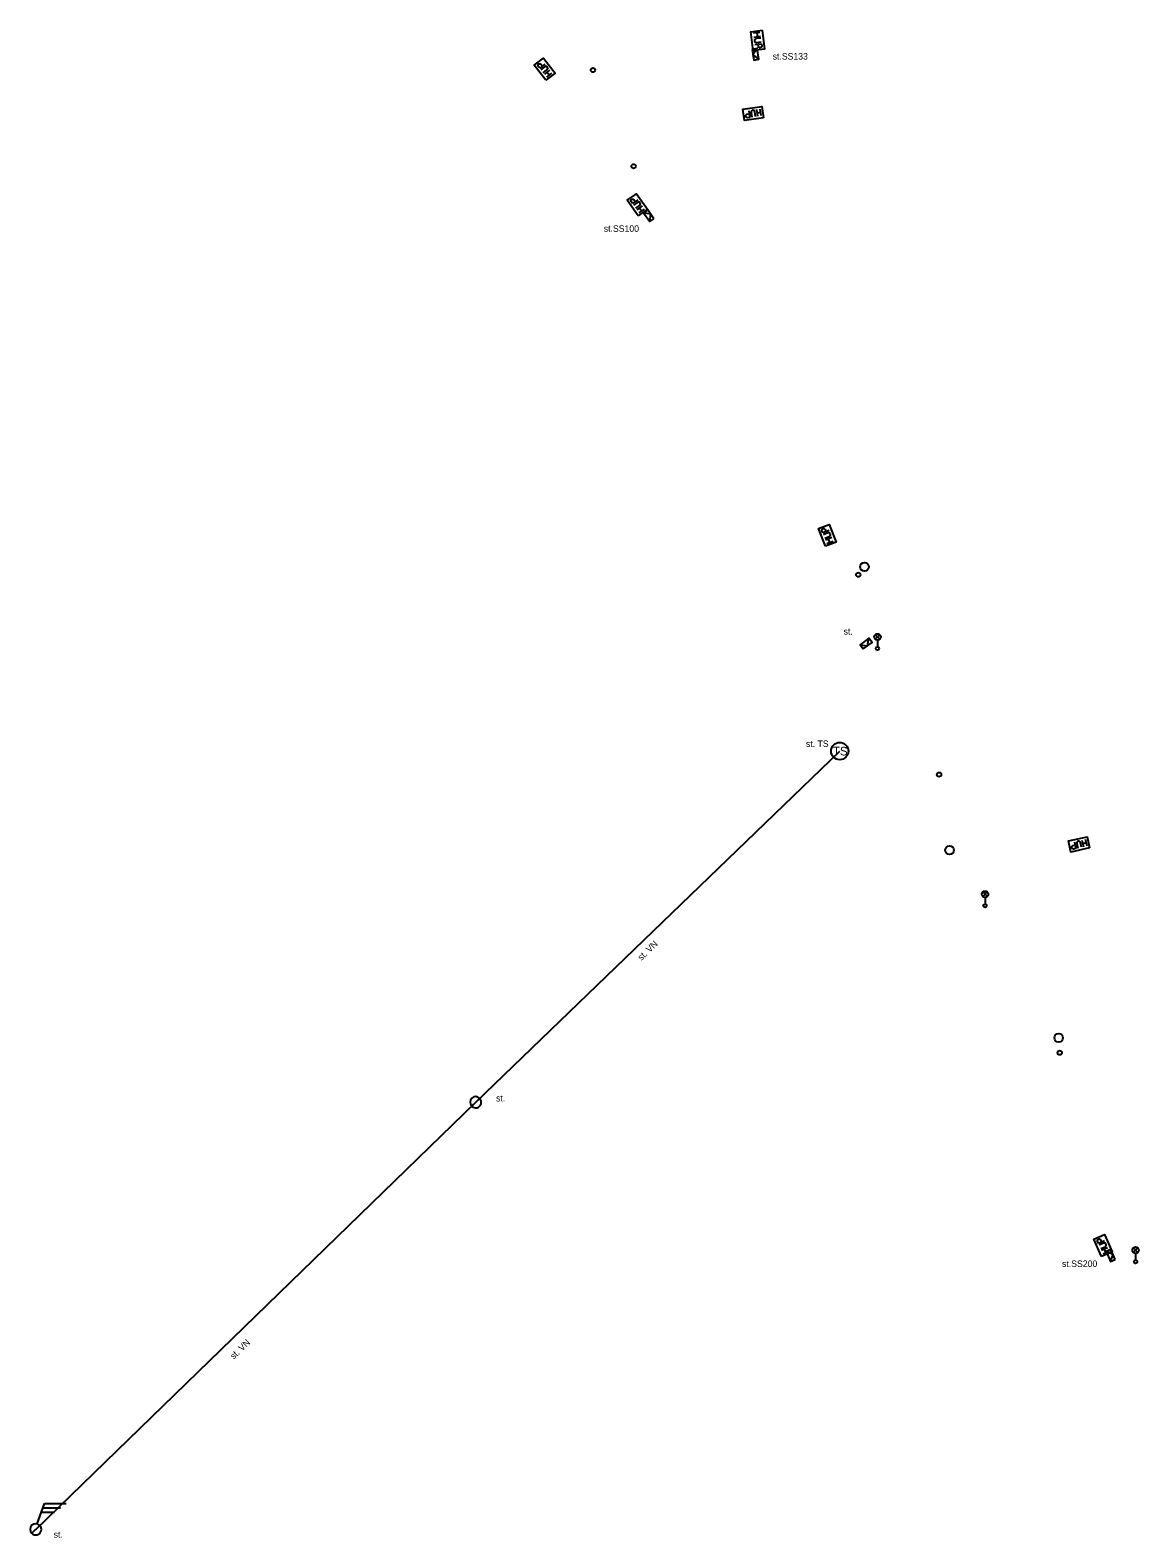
# Model space of a CAD drawing. Extents: x -762500 to -761250, y -1152983 to -1152297.
# Drawn here: x -761610 to -761481.9, y -1152711 to -1152536.8 of the extents above; entities that cross this region are included whole.
import ezdxf

# ---------------------------------------------------------------- set-up
doc = ezdxf.new("R2010")
doc.units = 0
for name, color, linetype in [('Vrstva 1', 7, 'Continuous'), ('Vrstva 2', 7, 'Continuous'), ('Vrstva 9', 7, 'Continuous')]:
    doc.layers.add(name, color=color, linetype=linetype)

msp = doc.modelspace()

# ---------------------------------------------------------------- linework, layer by layer
at = {"layer": 'Vrstva 1'}
for p, q in [((-761558.052, -1152660.189), (-761558.988, -1152661.091)), ((-761609.205, -1152709.33), (-761608.35, -1152706.98)), ((-761608.7, -1152707.98), (-761607.2, -1152707.98)), ((-761608.5, -1152707.48), (-761606.5, -1152707.48)), ((-761608.35, -1152706.98), (-761605.85, -1152706.98)), ((-761608.884, -1152709.527), (-761609.816, -1152710.433))]:
    msp.add_line(p, q, dxfattribs=at)
for points in [[(-761526.572, -1152539.012), (-761526.388, -1152540.248), (-761525.795, -1152540.16), (-761525.978, -1152538.924)], [(-761537.924, -1152558.573), (-761538.636, -1152557.547), (-761539.129, -1152557.889), (-761538.417, -1152558.916)], [(-761513.734, -1152608.269), (-761512.726, -1152607.531), (-761513.08, -1152607.047), (-761514.089, -1152607.785)], [(-761484.63, -1152678.793), (-761485.13, -1152677.647), (-761485.68, -1152677.887), (-761485.18, -1152679.033)]]:
    msp.add_lwpolyline(points, close=True, dxfattribs=at)
for points in [[(-761525.978, -1152538.924), (-761526.48, -1152539.63), (-761525.795, -1152540.16)], [(-761538.417, -1152558.916), (-761538.28, -1152558.06), (-761539.129, -1152557.889)], [(-761514.089, -1152607.785), (-761513.23, -1152607.9), (-761513.08, -1152607.047)], [(-761609.35, -1152709.98), (-761558.52, -1152660.64), (-761516.46, -1152620.08)], [(-761485.18, -1152679.033), (-761484.88, -1152678.22), (-761485.68, -1152677.887)]]:
    msp.add_lwpolyline(points, dxfattribs=at)
msp.add_circle((-761516.46, -1152620.08), 1, dxfattribs=at)
for centre, start, end in [((-761558.52, -1152660.64), 43.95968, 223.95968), ((-761558.52, -1152660.64), 223.95968, 43.95968), ((-761609.35, -1152709.98), 44.14761, 224.14761), ((-761609.35, -1152709.98), 224.14761, 44.14761)]:
    msp.add_arc(centre, 0.65, start, end, dxfattribs=at)
at = {"layer": 'Vrstva 9'}
for p, q in [((-761512.364, -1152607.158), (-761511.836, -1152606.63)), ((-761511.828, -1152607.155), (-761512.356, -1152606.626)), ((-761512.1, -1152607.27), (-761512.1, -1152608.02)), ((-761499.934, -1152636.878), (-761499.406, -1152636.35)), ((-761499.398, -1152636.875), (-761499.926, -1152636.346)), ((-761499.67, -1152636.99), (-761499.67, -1152637.74)), ((-761482.534, -1152677.988), (-761482.006, -1152677.46)), ((-761481.998, -1152677.985), (-761482.526, -1152677.456)), ((-761482.27, -1152678.1), (-761482.27, -1152678.85))]:
    msp.add_line(p, q, dxfattribs=at)
for points in [[(-761525.428, -1152536.794), (-761525.136, -1152538.975), (-761526.444, -1152539.15), (-761526.736, -1152536.97), (-761525.428, -1152536.794)], [(-761525.671, -1152537.049), (-761526.434, -1152537.151)], [(-761526.031, -1152537.097), (-761525.972, -1152537.535)], [(-761526.376, -1152537.589), (-761525.612, -1152537.487)], [(-761525.584, -1152537.703), (-761526.131, -1152537.776), (-761526.234, -1152537.822), (-761526.297, -1152537.899), (-761526.321, -1152537.996), (-761526.313, -1152538.058), (-761526.264, -1152538.145), (-761526.183, -1152538.198), (-761526.072, -1152538.215), (-761525.525, -1152538.141)], [(-761526.259, -1152538.46), (-761525.496, -1152538.357)], [(-761525.496, -1152538.357), (-761525.458, -1152538.641), (-761525.482, -1152538.737), (-761525.514, -1152538.774), (-761525.581, -1152538.815), (-761525.69, -1152538.829), (-761525.766, -1152538.808), (-761525.805, -1152538.78), (-761525.854, -1152538.694), (-761525.892, -1152538.41)], [(-761550.399, -1152542.578), (-761551.747, -1152540.839), (-761550.704, -1152540.031), (-761549.356, -1152541.769), (-761550.399, -1152542.578)], [(-761551.125, -1152541.192), (-761551.301, -1152540.966), (-761551.328, -1152540.871), (-761551.32, -1152540.823), (-761551.282, -1152540.754), (-761551.195, -1152540.687), (-761551.118, -1152540.667), (-761551.07, -1152540.671), (-761550.985, -1152540.721), (-761550.809, -1152540.947)], [(-761550.517, -1152540.721), (-761551.125, -1152541.192)], [(-761550.721, -1152541.714), (-761550.285, -1152541.376), (-761550.219, -1152541.285), (-761550.202, -1152541.187), (-761550.23, -1152541.091), (-761550.269, -1152541.041), (-761550.355, -1152540.99), (-761550.451, -1152540.985), (-761550.556, -1152541.027), (-761550.992, -1152541.365)], [(-761549.979, -1152541.415), (-761550.588, -1152541.886)], [(-761550.317, -1152542.236), (-761549.708, -1152541.764)], [(-761550.03, -1152542.013), (-761550.301, -1152541.664)], [(-761525.274, -1152546.91), (-761527.449, -1152547.24), (-761527.648, -1152545.935), (-761525.472, -1152545.605), (-761525.274, -1152546.91)], [(-761526.086, -1152545.976), (-761525.97, -1152546.737)], [(-761525.533, -1152546.671), (-761525.649, -1152545.91)], [(-761526.838, -1152546.869), (-761527.121, -1152546.912), (-761527.217, -1152546.889), (-761527.255, -1152546.859), (-761527.297, -1152546.792), (-761527.313, -1152546.684), (-761527.294, -1152546.607), (-761527.266, -1152546.567), (-761527.181, -1152546.517), (-761526.898, -1152546.474)], [(-761526.954, -1152546.108), (-761526.838, -1152546.869)], [(-761526.185, -1152546.77), (-761526.268, -1152546.224), (-761526.315, -1152546.122), (-761526.393, -1152546.06), (-761526.491, -1152546.038), (-761526.553, -1152546.047), (-761526.64, -1152546.098), (-761526.691, -1152546.179), (-761526.705, -1152546.291), (-761526.622, -1152546.836)], [(-761525.588, -1152546.312), (-761526.025, -1152546.378)], [(-761539.744, -1152558.25), (-761541.013, -1152556.452), (-761539.934, -1152555.691), (-761538.666, -1152557.489), (-761539.744, -1152558.25)], [(-761540.407, -1152556.833), (-761540.572, -1152556.599), (-761540.595, -1152556.503), (-761540.585, -1152556.455), (-761540.544, -1152556.388), (-761540.454, -1152556.325), (-761540.377, -1152556.308), (-761540.329, -1152556.315), (-761540.246, -1152556.369), (-761540.081, -1152556.602)], [(-761539.778, -1152556.389), (-761540.407, -1152556.833)], [(-761540.027, -1152557.372), (-761539.576, -1152557.054), (-761539.506, -1152556.966), (-761539.485, -1152556.869), (-761539.509, -1152556.771), (-761539.545, -1152556.72), (-761539.629, -1152556.665), (-761539.725, -1152556.656), (-761539.831, -1152556.693), (-761540.282, -1152557.011)], [(-761539.272, -1152557.106), (-761539.901, -1152557.55)], [(-761539.646, -1152557.912), (-761539.017, -1152557.468)], [(-761539.35, -1152557.702), (-761539.605, -1152557.341)], [(-761518.112, -1152596.413), (-761518.909, -1152594.362), (-761517.678, -1152593.885), (-761516.882, -1152595.935), (-761518.112, -1152596.413)], [(-761518.413, -1152594.878), (-761518.517, -1152594.611), (-761518.516, -1152594.512), (-761518.494, -1152594.468), (-761518.438, -1152594.414), (-761518.336, -1152594.374), (-761518.256, -1152594.376), (-761518.212, -1152594.394), (-761518.144, -1152594.467), (-761518.041, -1152594.733)], [(-761517.696, -1152594.599), (-761518.413, -1152594.878)], [(-761518.175, -1152595.493), (-761517.66, -1152595.294), (-761517.57, -1152595.226), (-761517.527, -1152595.136), (-761517.526, -1152595.036), (-761517.549, -1152594.977), (-761517.617, -1152594.904), (-761517.708, -1152594.871), (-761517.82, -1152594.881), (-761518.335, -1152595.081)], [(-761517.378, -1152595.418), (-761518.096, -1152595.697)], [(-761517.936, -1152596.109), (-761517.218, -1152595.83)], [(-761517.597, -1152595.977), (-761517.757, -1152595.565)], [(-761487.601, -1152631.261), (-761489.749, -1152631.736), (-761490.034, -1152630.448), (-761487.886, -1152629.972), (-761487.601, -1152631.261)], [(-761489.164, -1152631.325), (-761489.443, -1152631.387), (-761489.541, -1152631.371), (-761489.581, -1152631.343), (-761489.627, -1152631.279), (-761489.65, -1152631.172), (-761489.636, -1152631.094), (-761489.611, -1152631.053), (-761489.529, -1152630.997), (-761489.25, -1152630.935)], [(-761489.33, -1152630.574), (-761489.164, -1152631.325)], [(-761488.519, -1152631.183), (-761488.639, -1152630.644), (-761488.692, -1152630.545), (-761488.774, -1152630.488), (-761488.873, -1152630.472), (-761488.935, -1152630.486), (-761489.018, -1152630.542), (-761489.063, -1152630.627), (-761489.07, -1152630.739), (-761488.951, -1152631.278)], [(-761488.473, -1152630.384), (-761488.307, -1152631.136)], [(-761487.953, -1152630.686), (-761488.385, -1152630.781)], [(-761487.875, -1152631.04), (-761488.041, -1152630.288)], [(-761486.2, -1152678.466), (-761487.08, -1152676.45), (-761485.87, -1152675.922), (-761484.99, -1152677.938), (-761486.2, -1152678.466)], [(-761486.564, -1152676.945), (-761486.678, -1152676.683), (-761486.681, -1152676.583), (-761486.661, -1152676.539), (-761486.608, -1152676.482), (-761486.507, -1152676.438), (-761486.428, -1152676.437), (-761486.382, -1152676.453), (-761486.312, -1152676.523), (-761486.197, -1152676.785)], [(-761485.858, -1152676.637), (-761486.564, -1152676.945)], [(-761486.3, -1152677.55), (-761485.794, -1152677.329), (-761485.707, -1152677.257), (-761485.668, -1152677.166), (-761485.671, -1152677.066), (-761485.696, -1152677.008), (-761485.767, -1152676.937), (-761485.859, -1152676.909), (-761485.971, -1152676.924), (-761486.477, -1152677.144)], [(-761485.507, -1152677.441), (-761486.213, -1152677.749)], [(-761486.036, -1152678.154), (-761485.33, -1152677.847)], [(-761485.703, -1152678.009), (-761485.88, -1152677.604)]]:
    msp.add_lwpolyline(points, dxfattribs=at)
for centre, radius in [((-761544.97, -1152541.41), 0.25), ((-761540.27, -1152552.51), 0.25), ((-761514.31, -1152599.7), 0.25), ((-761513.61, -1152598.79), 0.5), ((-761512.1, -1152606.895), 0.375), ((-761512.1, -1152608.22), 0.2), ((-761504.97, -1152622.79), 0.25), ((-761503.76, -1152631.52), 0.5), ((-761499.67, -1152636.615), 0.375), ((-761499.67, -1152637.94), 0.2), ((-761491.16, -1152653.2), 0.5), ((-761491.03, -1152654.93), 0.25), ((-761482.27, -1152677.725), 0.375), ((-761482.27, -1152679.05), 0.2)]:
    msp.add_circle(centre, radius, dxfattribs=at)

# ---------------------------------------------------------------- texts
at = {"layer": 'Vrstva 1'}
msp.add_text('TS', height=1, dxfattribs=at).set_placement((-761517.253, -1152620.58))
at = {"layer": 'Vrstva 2'}
for s, p in [('st.SS133', (-761524.21, -1152540.19)), ('st.SS100', (-761543.72, -1152560.09)), ('st.', (-761516.01, -1152606.62)), ('st. TS', (-761520.36, -1152619.6)), ('st.', (-761556.17, -1152660.55)), ('st.SS200', (-761490.77, -1152679.67)), ('st.', (-761607.28, -1152710.95))]:
    msp.add_text(s, height=0.75, dxfattribs=at).set_placement(p)
for p in [(-761539.38, -1152644.33), (-761586.47, -1152690.38)]:
    msp.add_text('st. VN', height=0.75, rotation=43.95982, dxfattribs=at).set_placement(p)

doc.saveas('drawing.dxf')
